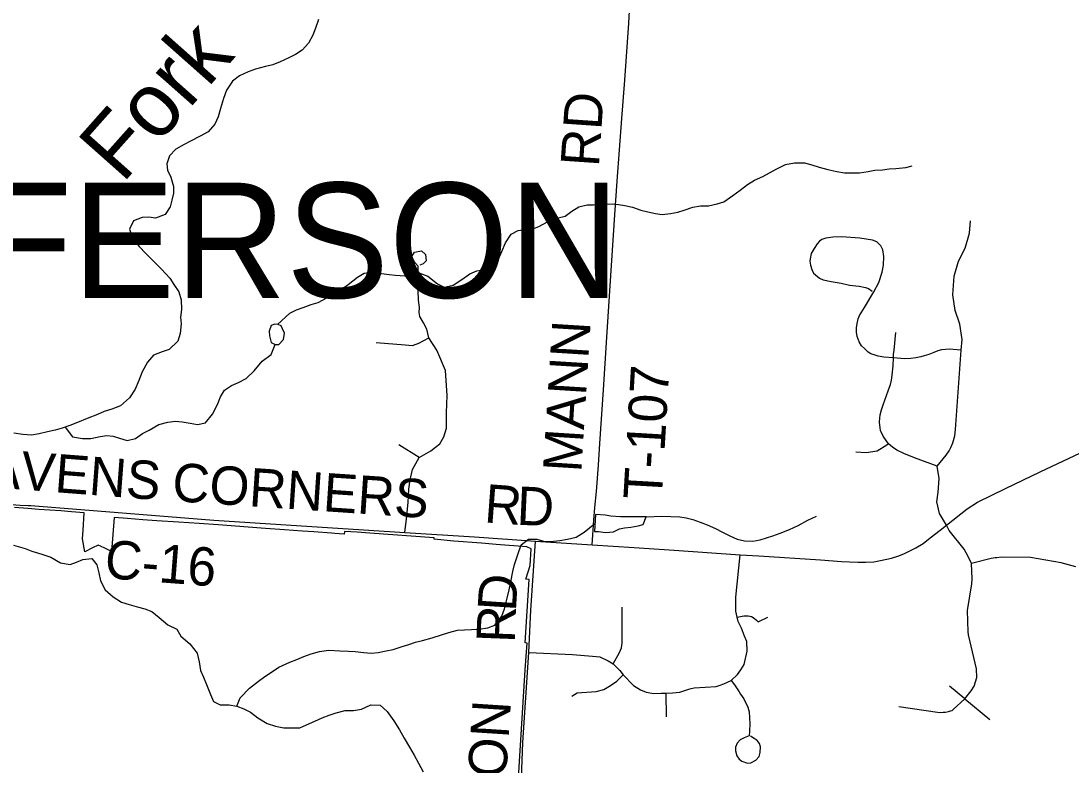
# Model space of a CAD drawing. Extents: x 208586767.6 to 208586821.4, y -134301046.9 to -134301022.9.
# Drawn here: x 208586781.515 to 208586783.069, y -134301030.059 to -134301028.957 of the extents above; entities that cross this region are included whole.
import ezdxf

# ---------------------------------------------------------------- set-up
doc = ezdxf.new("R2010")
doc.units = 0
for name, color, linetype in [('GM_X_Corporation', 7, 'Continuous'), ('GM_X_County_Road', 7, 'Continuous'), ('GM_X_County_Road_Text', 7, 'Continuous'), ('GM_X_Minor_Lake', 7, 'Continuous'), ('GM_X_Minor_River', 7, 'Continuous'), ('GM_X_Minor_River_Text', 7, 'Continuous'), ('GM_X_Township_Road', 7, 'Continuous'), ('GM_X_Township_Road_Text', 7, 'Continuous'), ('GM_X_Township_Text', 7, 'Continuous')]:
    doc.layers.add(name, color=color, linetype=linetype)

msp = doc.modelspace()

# ---------------------------------------------------------------- linework, layer by layer
at = {"layer": 'GM_X_Corporation'}
msp.add_lwpolyline([(208586782.2469, -134301030.1415), (208586782.2611, -134301029.9178), (208586782.2637, -134301029.878), (208586782.2609, -134301029.8778), (208586782.2668, -134301029.7838), (208586782.2621, -134301029.7835), (208586782.2682, -134301029.763), (208586782.2697, -134301029.7388), (208586782.2632, -134301029.7355), (208586782.2178, -134301029.7322), (208586782.1965, -134301029.73), (208586782.1556, -134301029.727), (208586782.1263, -134301029.7244), (208586782.1265, -134301029.7222), (208586782.0312, -134301029.7154), (208586782.0123, -134301029.7141), (208586781.9934, -134301029.7129), (208586781.9932, -134301029.7167), (208586781.9791, -134301029.7157), (208586781.9743, -134301029.7154), (208586781.9483, -134301029.7136), (208586781.9314, -134301029.7125), (208586781.9049, -134301029.7105), (208586781.8768, -134301029.7085), (208586781.851, -134301029.7066), (208586781.8325, -134301029.7052), (208586781.8068, -134301029.7032), (208586781.7787, -134301029.7011), (208586781.7479, -134301029.6992), (208586781.7159, -134301029.6972), (208586781.695, -134301029.6956), (208586781.6725, -134301029.6939), (208586781.6526, -134301029.6924), (208586781.6491, -134301029.7426), (208586781.6382, -134301029.7372), (208586781.6292, -134301029.7332), (208586781.6209, -134301029.7372), (208586781.6093, -134301029.7429), (208586781.606, -134301029.7237), (208586781.6068, -134301029.7111), (208586781.6085, -134301029.6851), (208586781.5899, -134301029.6838), (208586781.5738, -134301029.6825), (208586781.5412, -134301029.6801), (208586781.5249, -134301029.6789), (208586781.5056, -134301029.6775)], dxfattribs=at)
at = {"layer": 'GM_X_County_Road'}
for points in [[(208586782.7288, -134301029.7572), (208586782.7407, -134301029.758), (208586782.7533, -134301029.7585), (208586782.7646, -134301029.7585), (208586782.7769, -134301029.7577), (208586782.7869, -134301029.756), (208586782.803, -134301029.7524), (208586782.8138, -134301029.7491), (208586782.8224, -134301029.7455), (208586782.8391, -134301029.7371), (208586782.8497, -134301029.7306), (208586782.8604, -134301029.7225), (208586782.875, -134301029.7109), (208586782.8842, -134301029.7036), (208586782.9151, -134301029.6792), (208586782.93, -134301029.6695), (208586782.9716, -134301029.6493), (208586783.023, -134301029.6248), (208586783.0824, -134301029.5965)], [(208586781.406, -134301029.6657), (208586781.5137, -134301029.6737), (208586781.5257, -134301029.6744)], [(208586781.5257, -134301029.6744), (208586781.5297, -134301029.6746), (208586781.8004, -134301029.6962), (208586782.0828, -134301029.7142), (208586782.1862, -134301029.7209), (208586782.276, -134301029.7271), (208586782.3602, -134301029.7327)], [(208586782.2142, -134301030.7436), (208586782.2147, -134301030.7337), (208586782.2267, -134301030.5332), (208586782.2417, -134301030.2783), (208586782.2556, -134301030.0782), (208586782.2574, -134301030.0255), (208586782.2665, -134301029.8919), (208586782.2694, -134301029.8294), (208586782.276, -134301029.7271)], [(208586782.3602, -134301029.7327), (208586782.4222, -134301029.7368), (208586782.4814, -134301029.7404), (208586782.5792, -134301029.7473), (208586782.6067, -134301029.7491), (208586782.6981, -134301029.7551), (208586782.7288, -134301029.7572)]]:
    msp.add_lwpolyline(points, dxfattribs=at)
at = {"layer": 'GM_X_Minor_Lake'}
for points in [[(208586781.8953, -134301029.4066), (208586781.8904, -134301029.4059), (208586781.8851, -134301029.4077), (208586781.8824, -134301029.4161), (208586781.8827, -134301029.4233), (208586781.8853, -134301029.4331), (208586781.891, -134301029.4362), (208586781.8967, -134301029.4359), (208586781.9032, -134301029.4287), (208586781.9047, -134301029.4192), (208586781.9021, -134301029.4128), (208586781.8999, -134301029.4086)], [(208586781.8999, -134301029.4086), (208586781.8953, -134301029.4066)], [(208586782.3633, -134301029.713), (208586782.3694, -134301029.7127), (208586782.3796, -134301029.7142), (208586782.3918, -134301029.7132), (208586782.4005, -134301029.709), (208586782.4081, -134301029.7076), (208586782.4172, -134301029.7065), (208586782.4279, -134301029.7047), (208586782.4355, -134301029.7024), (208586782.4401, -134301029.6914), (208586782.4021, -134301029.6912), (208586782.3877, -134301029.6904), (208586782.3794, -134301029.6888), (208586782.3651, -134301029.6876)], [(208586782.3651, -134301029.6876), (208586782.3633, -134301029.713)], [(208586782.3633, -134301029.713), (208586782.3694, -134301029.7127), (208586782.3796, -134301029.7142), (208586782.3918, -134301029.7132), (208586782.4005, -134301029.709), (208586782.4081, -134301029.7076), (208586782.4172, -134301029.7065), (208586782.4279, -134301029.7047), (208586782.4355, -134301029.7024), (208586782.4401, -134301029.6914), (208586782.4021, -134301029.6912), (208586782.3877, -134301029.6904), (208586782.3794, -134301029.6888), (208586782.365, -134301029.6876)]]:
    msp.add_lwpolyline(points, dxfattribs=at)
at = {"layer": 'GM_X_Minor_River'}
for points in [[(208586781.9551, -134301028.9547), (208586781.9508, -134301028.9675), (208586781.9466, -134301028.9781), (208586781.9405, -134301028.9899), (208586781.9309, -134301029.0004), (208586781.921, -134301029.0068), (208586781.9115, -134301029.0117), (208586781.8985, -134301029.0177), (208586781.8875, -134301029.0222), (208586781.8765, -134301029.0244), (208586781.862, -134301029.0285), (208586781.851, -134301029.0326), (208586781.8381, -134301029.0382), (208586781.8281, -134301029.0461), (208586781.8189, -134301029.0593), (208586781.8147, -134301029.0718), (208586781.8104, -134301029.0866), (208586781.8066, -134301029.0991), (208586781.8019, -134301029.1097), (208586781.792, -134301029.1214), (208586781.7802, -134301029.1278), (208586781.7657, -134301029.1349), (208586781.7562, -134301029.1398), (208586781.744, -134301029.1469), (208586781.7345, -134301029.1568), (208586781.7306, -134301029.1685), (208586781.7317, -134301029.178), (208586781.7365, -134301029.1883), (208586781.7406, -134301029.2023), (208586781.7406, -134301029.2118), (208586781.7382, -134301029.2224), (208586781.7355, -134301029.2323), (208586781.7282, -134301029.2436), (208586781.7142, -134301029.2488), (208586781.7043, -134301029.2476), (208586781.6944, -134301029.248), (208586781.6815, -134301029.2532), (208586781.6757, -134301029.2653), (208586781.6802, -134301029.2794), (208586781.69, -134301029.2912), (208586781.6998, -134301029.3015)], [(208586781.8947, -134301029.4065), (208586781.9129, -134301029.3897), (208586781.9228, -134301029.3848), (208586781.9327, -134301029.3811), (208586781.9445, -134301029.377), (208586781.9548, -134301029.374), (208586781.9673, -134301029.3668), (208586781.9768, -134301029.3616), (208586781.9883, -134301029.3552), (208586781.9989, -134301029.3473), (208586782.0131, -134301029.3364), (208586782.0226, -134301029.3304), (208586782.0359, -134301029.3285), (208586782.0484, -134301029.3309), (208586782.0598, -134301029.3325), (208586782.0692, -134301029.3333), (208586782.0829, -134301029.3345), (208586782.0947, -134301029.3327), (208586782.1049, -134301029.3305), (208586782.1167, -134301029.3347), (208586782.131, -134301029.3462), (208586782.1412, -134301029.3512), (208586782.1542, -134301029.3482), (208586782.1671, -134301029.3399), (208586782.1789, -134301029.3313), (208586782.1896, -134301029.3272), (208586782.2006, -134301029.325), (208586782.2105, -134301029.3216), (208586782.22, -134301029.3133), (208586782.2266, -134301029.2986), (208586782.232, -134301029.2857), (208586782.2404, -134301029.2725), (208586782.2507, -134301029.2672), (208586782.2602, -134301029.2657), (208586782.2712, -134301029.2651), (208586782.2811, -134301029.2613), (208586782.294, -134301029.2546), (208586782.3096, -134301029.2486), (208586782.3203, -134301029.246), (208586782.3298, -134301029.2388), (208586782.3401, -134301029.2324), (208586782.3526, -134301029.2295), (208586782.3621, -134301029.2292), (208586782.375, -134301029.2285), (208586782.3895, -134301029.2278), (208586782.399, -134301029.2286), (208586782.4084, -134301029.2302), (208586782.4198, -134301029.2329), (208586782.4323, -134301029.2372), (208586782.4425, -134301029.2395), (208586782.4539, -134301029.2422), (208586782.4634, -134301029.2434), (208586782.4759, -134301029.242), (208586782.4869, -134301029.2402), (208586782.4964, -134301029.2372), (208586782.509, -134301029.2327), (208586782.5204, -134301029.2309), (208586782.5322, -134301029.2306), (208586782.5451, -134301029.228), (208586782.555, -134301029.225), (208586782.5683, -134301029.2156), (208586782.579, -134301029.2077), (208586782.59, -134301029.1994), (208586782.6003, -134301029.1926), (208586782.6125, -134301029.1874), (208586782.6224, -134301029.1821), (208586782.6323, -134301029.1765), (208586782.646, -134301029.1698), (208586782.6593, -134301029.1672), (208586782.6741, -134301029.1673), (208586782.6851, -134301029.17), (208586782.6957, -134301029.1735), (208586782.7086, -134301029.177), (208586782.7222, -134301029.1801), (208586782.7336, -134301029.182), (208586782.745, -134301029.1821), (208586782.7556, -134301029.1818), (208586782.7682, -134301029.18), (208586782.7784, -134301029.1781), (208586782.7898, -134301029.1775), (208586782.7993, -134301029.176), (208586782.8096, -134301029.1757), (208586782.824, -134301029.1739), (208586782.8335, -134301029.1716)], [(208586781.6998, -134301029.3015), (208586781.71, -134301029.3118), (208586781.7228, -134301029.3244), (208586781.7352, -134301029.3378), (208586781.7412, -134301029.3473), (208586781.7484, -134301029.3583), (208586781.7521, -134301029.3697), (208586781.7524, -134301029.3842), (208586781.7512, -134301029.3955), (208586781.7519, -134301029.4054), (208586781.7507, -134301029.4198), (208586781.7468, -134301029.4312), (208586781.7342, -134301029.4436), (208586781.7239, -134301029.447), (208586781.711, -134301029.4518), (208586781.7022, -134301029.4624), (208586781.6941, -134301029.4764), (208586781.6891, -134301029.4893), (208586781.6841, -134301029.5022), (208586781.6753, -134301029.515), (208586781.6623, -134301029.5271), (208586781.6494, -134301029.5316), (208586781.638, -134301029.5353), (208586781.6281, -134301029.5398), (208586781.6129, -134301029.5458), (208586781.5984, -134301029.5517), (208586781.5874, -134301029.5562), (208586781.576, -134301029.56), (208586781.5657, -134301029.5629), (208586781.5543, -134301029.5655), (208586781.5417, -134301029.5685), (208586781.5304, -134301029.5703), (208586781.5178, -134301029.5695), (208586781.5042, -134301029.5675)], [(208586781.5802, -134301029.5586), (208586781.5914, -134301029.5726), (208586781.6062, -134301029.5753), (208586781.6184, -134301029.575), (208586781.6321, -134301029.5724), (208586781.6419, -134301029.5706), (208586781.6514, -134301029.5718), (208586781.6609, -134301029.5745), (208586781.6719, -134301029.578), (208586781.6844, -134301029.575), (208586781.6947, -134301029.5679), (208586781.7046, -134301029.563), (208586781.7187, -134301029.5547), (208586781.732, -134301029.551), (208586781.7438, -134301029.5496), (208586781.7536, -134301029.5504), (208586781.7654, -134301029.5527), (208586781.776, -134301029.5547), (208586781.7878, -134301029.5521), (208586781.7985, -134301029.5393), (208586781.8058, -134301029.5249), (208586781.81, -134301029.5135), (208586781.8162, -134301029.5037), (208586781.8265, -134301029.4969), (208586781.8367, -134301029.4924), (208586781.8482, -134301029.4864), (208586781.86, -134301029.4751), (208586781.8719, -134301029.4608), (208586781.8852, -134301029.451), (208586781.8911, -134301029.4362)], [(208586781.8345, -134301029.9717), (208586781.8391, -134301029.9592), (208586781.8529, -134301029.9449), (208586781.8662, -134301029.9343), (208586781.8758, -134301029.9275), (208586781.8872, -134301029.9204), (208586781.8967, -134301029.914), (208586781.9127, -134301029.9065), (208586781.923, -134301029.9024), (208586781.9333, -134301029.8979), (208586781.9443, -134301029.8938), (208586781.9568, -134301029.8905), (208586781.9705, -134301029.8886), (208586781.9868, -134301029.8895), (208586781.9994, -134301029.89), (208586782.0096, -134301029.8904), (208586782.0221, -134301029.892), (208586782.0331, -134301029.8928), (208586782.0434, -134301029.8921), (208586782.0555, -134301029.8895), (208586782.0654, -134301029.8877), (208586782.0791, -134301029.8832), (208586782.0886, -134301029.8802), (208586782.0985, -134301029.8769), (208586782.1091, -134301029.8743), (208586782.1232, -134301029.8702), (208586782.1369, -134301029.8657), (208586782.1479, -134301029.8624), (208586782.1608, -134301029.859), (208586782.1711, -134301029.8583), (208586782.1817, -134301029.858), (208586782.1924, -134301029.8573), (208586782.2057, -134301029.8555), (208586782.2159, -134301029.8514), (208586782.2266, -134301029.8382), (208586782.2305, -134301029.8272), (208586782.2344, -134301029.8117), (208586782.2375, -134301029.7992), (208586782.2399, -134301029.7874), (208586782.2426, -134301029.7719), (208586782.2453, -134301029.7616), (208586782.25, -134301029.7472), (208586782.255, -134301029.7325), (208586782.2657, -134301029.7242), (208586782.2782, -134301029.7243), (208586782.2881, -134301029.727), (208586782.2983, -134301029.7278), (208586782.312, -134301029.7264), (208586782.3234, -134301029.7245), (208586782.3363, -134301029.7212), (208586782.3481, -134301029.714), (208586782.3641, -134301029.701)], [(208586782.4399, -134301029.6914), (208586782.4633, -134301029.6901), (208586782.4765, -134301029.6909), (208586782.4898, -134301029.6914), (208586782.4993, -134301029.6926), (208586782.5088, -134301029.6953), (208586782.5201, -134301029.6991), (208586782.5304, -134301029.703), (208586782.5428, -134301029.7084), (208586782.5531, -134301029.7141), (208586782.5636, -134301029.7191), (208586782.5746, -134301029.7241), (208586782.5856, -134301029.7268), (208586782.5978, -134301029.7273), (208586782.6084, -134301029.7251), (208586782.6179, -134301029.7225), (208586782.6274, -134301029.7191), (208586782.6381, -134301029.7154), (208586782.6521, -134301029.7098), (208586782.6647, -134301029.7042), (208586782.6792, -134301029.6963), (208586782.6921, -134301029.6903)], [(208586781.5039, -134301029.7333), (208586781.521, -134301029.738), (208586781.5308, -134301029.7422), (208586781.546, -134301029.7465), (208586781.5592, -134301029.7511), (208586781.5736, -134301029.7595), (208586781.5876, -134301029.7619), (208586781.5971, -134301029.7585), (208586781.6066, -134301029.7544), (208586781.6199, -134301029.753), (208586781.6271, -134301029.7625), (208586781.63, -134301029.7743), (208586781.6326, -134301029.7861), (208586781.6397, -134301029.7994), (208586781.6511, -134301029.8097), (208586781.6635, -134301029.8174), (208586781.6749, -134301029.8209), (208586781.6889, -134301029.8247), (208586781.6984, -134301029.8275), (208586781.7086, -134301029.8313), (208586781.7192, -134301029.8401), (208586781.732, -134301029.8512), (208586781.7453, -134301029.8577), (208586781.7517, -134301029.868), (208586781.7649, -134301029.8791), (208586781.7754, -134301029.8928), (208586781.7787, -134301029.9057), (208586781.7806, -134301029.9186), (208586781.7851, -134301029.9285), (208586781.7895, -134301029.9396), (208586781.7955, -134301029.954), (208586781.7996, -134301029.9647), (208586781.8099, -134301029.9697), (208586781.8231, -134301029.9694), (208586781.8345, -134301029.9717), (208586781.8447, -134301029.9756), (208586781.8546, -134301029.9805), (208586781.8655, -134301029.9886), (208586781.8791, -134301029.997), (208586781.8913, -134301030.0009), (208586781.9041, -134301030.0036), (208586781.9273, -134301030.0037), (208586781.9372, -134301029.9993), (208586781.9497, -134301029.9936), (208586781.9604, -134301029.9888), (208586781.9707, -134301029.985), (208586781.9813, -134301029.9813), (208586781.9946, -134301029.978), (208586782.0068, -134301029.9777), (208586782.0186, -134301029.9758), (208586782.0326, -134301029.9695), (208586782.0463, -134301029.9699), (208586782.0569, -134301029.9795), (208586782.0666, -134301029.9932), (208586782.0749, -134301030.0065), (208586782.0817, -134301030.0191), (208586782.0899, -134301030.0324), (208586782.0967, -134301030.0442), (208586782.1031, -134301030.056), (208586782.1102, -134301030.0686)]]:
    msp.add_lwpolyline(points, dxfattribs=at)
at = {"layer": 'GM_X_Township_Road'}
for p, q in [((208586782.1039, -134301029.6033), (208586782.074, -134301029.5846)), ((208586782.9113, -134301029.9605), (208586782.8886, -134301029.9418)), ((208586782.4703, -134301029.9872), (208586782.4696, -134301029.9523)), ((208586782.9113, -134301029.9605), (208586782.9485, -134301029.9913))]:
    msp.add_line(p, q, dxfattribs=at)
for points in [[(208586782.3602, -134301029.7327), (208586782.3624, -134301029.6962), (208586782.3641, -134301029.6772), (208586782.3663, -134301029.6535), (208586782.3696, -134301029.6145), (208586782.3713, -134301029.5826), (208586782.3766, -134301029.5032), (208586782.3817, -134301029.4252), (208586782.3867, -134301029.349), (208586782.3937, -134301029.2442), (208586782.3971, -134301029.1942), (208586782.4042, -134301029.1014), (208586782.4082, -134301029.0446), (208586782.4141, -134301028.9603), (208586782.4175, -134301028.9056)], [(208586782.8703, -134301029.6164), (208586782.884, -134301029.5997), (208586782.8882, -134301029.5936), (208586782.891, -134301029.5885), (208586782.8939, -134301029.5815), (208586782.8969, -134301029.5713), (208586782.8979, -134301029.562), (208586782.9062, -134301029.4446), (208586782.9073, -134301029.4289), (208586782.9042, -134301029.4061), (208586782.897, -134301029.3855), (208586782.8939, -134301029.3627), (208586782.8958, -134301029.3351), (208586782.9021, -134301029.3129), (208586782.9121, -134301029.2935), (208586782.9184, -134301029.2714), (208586782.9197, -134301029.2529)], [(208586782.7768, -134301029.3582), (208586782.7844, -134301029.3442), (208586782.7893, -134301029.3292), (208586782.791, -134301029.3184), (208586782.7918, -134301029.3057), (208586782.7903, -134301029.2959), (208586782.7872, -134301029.2902), (208586782.7812, -134301029.2841), (208586782.7749, -134301029.2815), (208586782.7562, -134301029.2788), (208586782.7291, -134301029.2766), (208586782.716, -134301029.2773), (208586782.7058, -134301029.2787), (208586782.7001, -134301029.2804), (208586782.6963, -134301029.2832), (208586782.6931, -134301029.2868), (208586782.6884, -134301029.2938), (208586782.6842, -134301029.3012), (208586782.6825, -134301029.3091), (208586782.6823, -134301029.3129), (208586782.6829, -134301029.3188), (208586782.6851, -134301029.3249), (208586782.6876, -134301029.3304), (208586782.6965, -134301029.3381), (208586782.7018, -134301029.3402), (208586782.7135, -134301029.3429), (208586782.7285, -134301029.3455), (208586782.7408, -134301029.348), (208586782.7552, -134301029.3499), (208586782.7647, -134301029.3516), (208586782.769, -134301029.3531), (208586782.7742, -134301029.3571)], [(208586782.1031, -134301029.3687), (208586782.1022, -134301029.3476), (208586782.1025, -134301029.32), (208586782.097, -134301029.3144), (208586782.0932, -134301029.3058), (208586782.097, -134301029.2996), (208586782.1077, -134301029.2975), (208586782.1137, -134301029.3029), (208586782.1143, -134301029.3123), (208586782.1101, -134301029.3168), (208586782.1053, -134301029.3186)], [(208586782.9062, -134301029.4446), (208586782.8941, -134301029.4434), (208586782.8882, -134301029.4432), (208586782.8829, -134301029.4434), (208586782.877, -134301029.444), (208586782.8715, -134301029.4453), (208586782.8658, -134301029.4478), (208586782.8583, -134301029.4508), (208586782.8514, -134301029.4527), (208586782.8465, -134301029.4544), (208586782.8391, -134301029.4559), (208586782.8316, -134301029.4567), (208586782.8223, -134301029.4571), (208586782.8057, -134301029.4556), (208586782.7916, -134301029.4546), (208586782.7831, -134301029.4533), (208586782.7774, -134301029.4516), (208586782.7726, -134301029.4501), (208586782.7683, -134301029.4472), (208586782.7628, -134301029.4419), (208586782.7588, -134301029.4378), (208586782.755, -134301029.4321), (208586782.7524, -134301029.4243), (208586782.7514, -134301029.4179), (208586782.7511, -134301029.4116), (208586782.7522, -134301029.4048), (208586782.7535, -134301029.3982), (208586782.7556, -134301029.3932), (208586782.7628, -134301029.3815), (208586782.7768, -134301029.3582)], [(208586782.0828, -134301029.7142), (208586782.0852, -134301029.6942), (208586782.0876, -134301029.67), (208586782.089, -134301029.6503), (208586782.0908, -134301029.6365), (208586782.0942, -134301029.621), (208586782.1039, -134301029.6033), (208586782.1108, -134301029.5995), (208586782.1212, -134301029.5937), (208586782.1284, -134301029.5881), (208586782.1349, -134301029.5833), (208586782.1405, -134301029.5729), (208586782.1447, -134301029.5598), (208586782.1447, -134301029.537), (208586782.1457, -134301029.5114), (208586782.1433, -134301029.4746), (208586782.1302, -134301029.4444), (208586782.1184, -134301029.4261), (208586782.1154, -134301029.4132), (208586782.1105, -134301029.4041), (208586782.1051, -134301029.3946), (208586782.104, -134301029.3889), (208586782.1048, -134301029.3814), (208586782.1032, -134301029.3704), (208586782.1031, -134301029.3687)], [(208586782.8703, -134301029.6164), (208586782.837, -134301029.6037), (208586782.8213, -134301029.5972), (208586782.8107, -134301029.5925), (208586782.8043, -134301029.5883), (208586782.7984, -134301029.583), (208586782.7908, -134301029.572), (208586782.7868, -134301029.5635), (208586782.7861, -134301029.5593), (208586782.7853, -134301029.5512), (208586782.7855, -134301029.5453), (208586782.7863, -134301029.54), (208586782.788, -134301029.5326), (208586782.7906, -134301029.5253), (208586782.7982, -134301029.5048), (208586782.8014, -134301029.4953), (208586782.8028, -134301029.4891), (208586782.8039, -134301029.4817), (208586782.8052, -134301029.4675), (208586782.8057, -134301029.4556), (208586782.8058, -134301029.4509), (208586782.8069, -134301029.4445), (208586782.8093, -134301029.4183)], [(208586782.0403, -134301029.4333), (208586782.0835, -134301029.4364), (208586782.0942, -134301029.4375), (208586782.1035, -134301029.434), (208586782.1184, -134301029.4261)], [(208586782.7984, -134301029.583), (208586782.7961, -134301029.5852), (208586782.7819, -134301029.5938), (208586782.7655, -134301029.5964), (208586782.7503, -134301029.5957)], [(208586782.8842, -134301029.7036), (208586782.8742, -134301029.6862), (208586782.8701, -134301029.6688), (208586782.8721, -134301029.6549), (208586782.8735, -134301029.6345), (208586782.8703, -134301029.6164)], [(208586782.814, -134301029.9721), (208586782.8712, -134301029.9805), (208586782.8755, -134301029.981), (208586782.8795, -134301029.9806), (208586782.883, -134301029.9803), (208586782.8874, -134301029.9795), (208586782.8903, -134301029.9785), (208586782.8925, -134301029.9778), (208586782.8942, -134301029.9765), (208586782.9113, -134301029.9605), (208586782.9208, -134301029.949), (208586782.9255, -134301029.9417), (208586782.9291, -134301029.9292), (208586782.9285, -134301029.9162), (208586782.9167, -134301029.8661), (208586782.9164, -134301029.8615), (208586782.9153, -134301029.8301), (208586782.9216, -134301029.7904), (208586782.9224, -134301029.783), (208586782.9213, -134301029.7603), (208586782.9162, -134301029.7501), (208586782.9106, -134301029.7389), (208586782.8885, -134301029.7116), (208586782.8842, -134301029.7036)], [(208586782.2665, -134301029.8919), (208586782.3308, -134301029.8951), (208586782.3607, -134301029.8976), (208586782.3716, -134301029.8986), (208586782.3839, -134301029.9046), (208586782.3913, -134301029.9088), (208586782.4011, -134301029.9186), (208586782.4058, -134301029.9249), (208586782.4212, -134301029.941), (208586782.4315, -134301029.9474), (208586782.4401, -134301029.9506), (208586782.4513, -134301029.9525), (208586782.4621, -134301029.9523), (208586782.4696, -134301029.9523), (208586782.479, -134301029.9517), (208586782.4899, -134301029.9508), (208586782.5033, -134301029.9463), (208586782.5065, -134301029.9453), (208586782.5109, -134301029.9442), (208586782.5435, -134301029.9423), (208586782.5495, -134301029.9406), (208586782.5548, -134301029.9382), (208586782.5655, -134301029.9335), (208586782.5749, -134301029.9244), (208586782.58, -134301029.9178), (208586782.5851, -134301029.91), (208586782.5894, -134301029.8902), (208586782.5889, -134301029.876), (208586782.5857, -134301029.8681), (208586782.581, -134301029.8562), (208586782.5761, -134301029.8463), (208586782.5745, -134301029.8398), (208586782.5727, -134301029.8307), (208586782.5727, -134301029.8101), (208586782.5792, -134301029.7473)], [(208586783.0756, -134301029.765), (208586783.0541, -134301029.7594), (208586783.0084, -134301029.7513), (208586782.965, -134301029.7511), (208586782.9587, -134301029.7518), (208586782.9562, -134301029.7521), (208586782.9505, -134301029.7528), (208586782.9213, -134301029.7603)], [(208586782.3913, -134301029.9088), (208586782.4007, -134301029.8922), (208586782.4034, -134301029.885), (208586782.4046, -134301029.8782), (208586782.4046, -134301029.8248)], [(208586782.5745, -134301029.8398), (208586782.5845, -134301029.8378), (208586782.591, -134301029.8377), (208586782.5957, -134301029.8387), (208586782.5999, -134301029.8414), (208586782.603, -134301029.8443), (208586782.6057, -134301029.8467), (208586782.62, -134301029.8396)], [(208586782.3298, -134301029.9569), (208586782.3378, -134301029.9516), (208586782.366, -134301029.9499), (208586782.3772, -134301029.9469), (208586782.3871, -134301029.941), (208586782.3964, -134301029.9343), (208586782.4058, -134301029.9249)], [(208586782.5655, -134301029.9335), (208586782.5708, -134301029.9397), (208586782.5776, -134301029.9504), (208586782.5797, -134301029.9535)], [(208586782.5797, -134301029.9535), (208586782.5845, -134301029.9608), (208586782.5906, -134301029.973), (208586782.5923, -134301029.98), (208586782.5934, -134301029.9975), (208586782.5931, -134301030.0083), (208586782.5923, -134301030.0156), (208586782.5848, -134301030.0186)], [(208586782.5848, -134301030.0186), (208586782.5791, -134301030.0215), (208586782.5744, -134301030.0263), (208586782.5723, -134301030.0324), (208586782.572, -134301030.0374), (208586782.5739, -134301030.0448), (208586782.5774, -134301030.0498), (208586782.5815, -134301030.0529), (208586782.59, -134301030.0557), (208586782.5947, -134301030.0552), (208586782.6023, -134301030.0512), (208586782.6071, -134301030.046), (208586782.6086, -134301030.0399), (208586782.6089, -134301030.0316), (208586782.6076, -134301030.0268), (208586782.6041, -134301030.0225), (208586782.5997, -134301030.0194), (208586782.5944, -134301030.0161)]]:
    msp.add_lwpolyline(points, dxfattribs=at)

# ---------------------------------------------------------------- texts
at = {"layer": 'GM_X_County_Road_Text'}
for s, height, rotation, p in [('HAVENS', 0.05682, 355.6141, (208586781.4079, -134301029.6426)), ('CORNERS', 0.05682, 356.1486, (208586781.7375, -134301029.6677)), ('R', 0.0568, 355.7968, (208586782.1994, -134301029.6993)), ('D', 0.0568, 357.4403, (208586782.2477, -134301029.7028)), ('C-16', 0.05682, 355.55, (208586781.6375, -134301029.7817)), ('D', 0.0568, 86.3584, (208586782.2471, -134301029.8322)), ('R', 0.0568, 87.802, (208586782.2454, -134301029.8784)), ('STATION', 0.05682, 86.3005, (208586782.2187, -134301030.2936))]:
    msp.add_text(s, height=height, rotation=rotation, dxfattribs=at).set_placement(p)
at = {"layer": 'GM_X_Minor_River_Text'}
msp.add_text('Fork', height=0.09469, rotation=48.4208, dxfattribs=at).set_placement((208586781.6649, -134301029.1991))
at = {"layer": 'GM_X_Township_Road_Text'}
for s, rotation, p in [('RD', 86.0551, (208586782.3699, -134301029.1739)), ('MANN', 86.4125, (208586782.3439, -134301029.6261)), ('T-107', 86.6655, (208586782.4629, -134301029.6668))]:
    msp.add_text(s, height=0.05682, rotation=rotation, dxfattribs=at).set_placement(p)
at = {"layer": 'GM_X_Township_Text'}
msp.add_text('JEFFERSON', height=0.17045, rotation=0, dxfattribs=at).set_placement((208586781.0463, -134301029.367))

doc.saveas('drawing.dxf')
